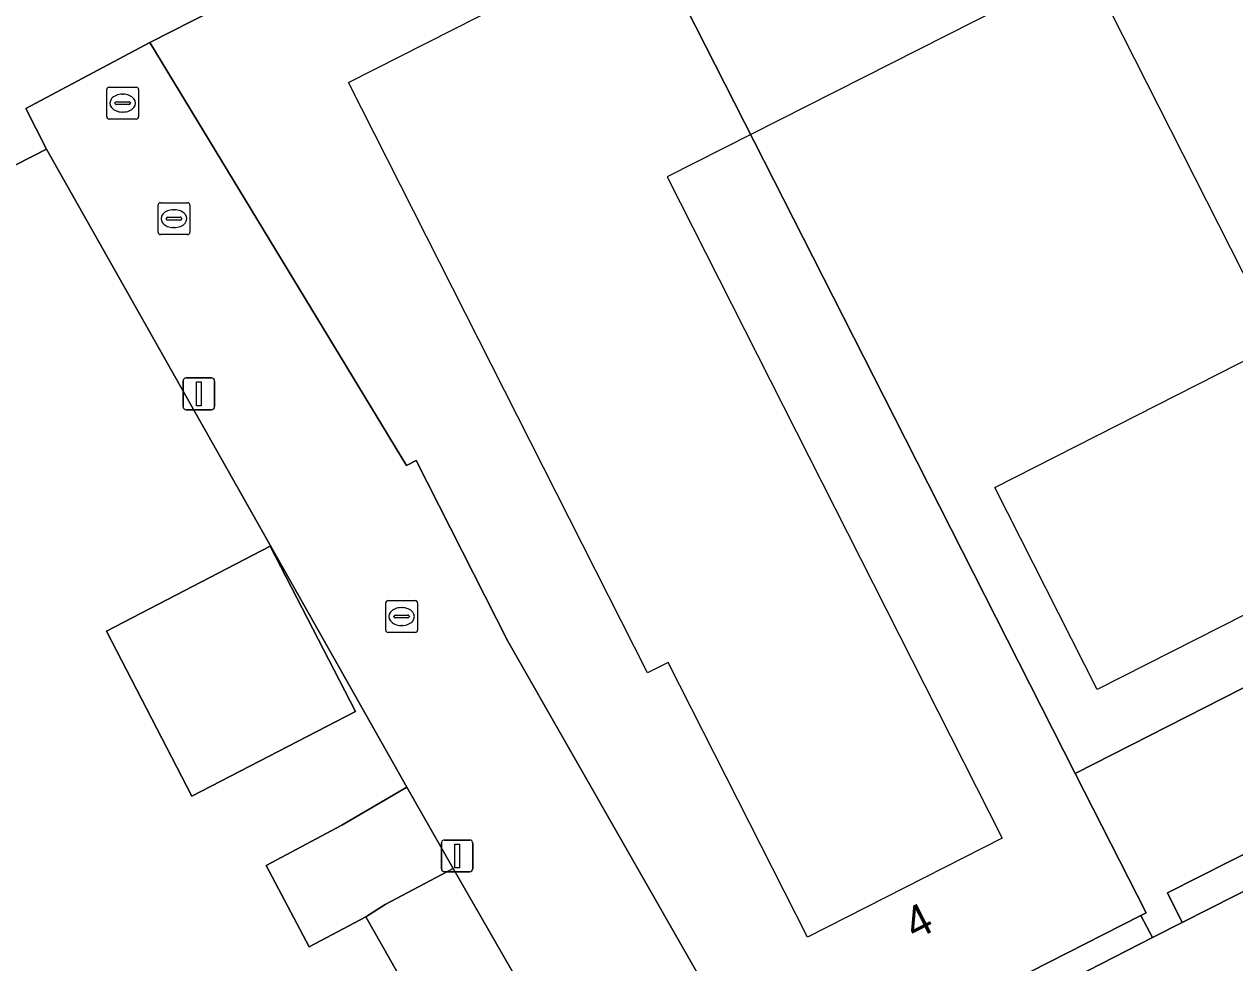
# Model space of a CAD drawing. Extents: x 159888 to 160761, y 384031 to 384750.
# Drawn here: x 160531.08 to 160569.11, y 384304.54 to 384334.01 of the extents above; entities that cross this region are included whole.
import ezdxf

# ---------------------------------------------------------------- set-up
doc = ezdxf.new("R2010")
doc.units = 0
for name, color, linetype in [('IMGEO_Erf', 7, 'Continuous'), ('IMGEO_Kolk', 7, 'Continuous'), ('IMGEO_Lichtmast', 7, 'Continuous'), ('IMGEO_Pand', 7, 'Continuous'), ('IMGEO_Pand_nummerreeks', 7, 'Continuous'), ('IMGEO_Pand_vergunning_verleend', 7, 'Continuous'), ('IMGEO_Rijbaan_lokaal_open', 7, 'Continuous'), ('IMGEO_Rioolput', 7, 'Continuous'), ('IMGEO_Voetpad_open', 7, 'Continuous')]:
    doc.layers.add(name, color=color, linetype=linetype)

msp = doc.modelspace()

# ---------------------------------------------------------------- linework, layer by layer
at = {"layer": 'IMGEO_Erf'}
for points in [[(160530.86, 384299.884), (160531.135, 384299.401), (160533.646, 384295.03), (160536.236, 384296.185), (160542.794, 384299.585), (160544.644, 384300.668), (160544.79, 384300.753), (160541.82, 384305.981), (160540.039, 384305.037), (160538.682, 384307.598), (160541.063, 384308.86), (160543.1, 384310.052), (160531.789, 384330.089), (160529.359, 384328.855)], [(160575.166, 384316.112), (160564.1, 384310.488), (160566.326, 384306.106), (160566.162, 384306.023), (160566.53, 384305.339), (160567.462, 384305.807), (160566.993, 384306.736), (160571.974, 384309.253)]]:
    msp.add_lwpolyline(points, dxfattribs=at)
msp.add_lwpolyline([(160538.814, 384317.617), (160541.492, 384312.435), (160536.346, 384309.775), (160533.668, 384314.957)], close=True, dxfattribs=at)
at = {"layer": 'IMGEO_Kolk'}
for p, q in [((160535.288, 384327.479), (160535.288, 384328.331)), ((160535.363, 384328.405), (160536.215, 384328.405)), ((160535.776, 384328.185), (160535.801, 384328.185)), ((160536.289, 384328.331), (160536.289, 384327.479)), ((160535.547, 384327.899), (160535.547, 384327.911)), ((160535.985, 384327.862), (160535.587, 384327.862)), ((160535.59, 384327.948), (160535.988, 384327.948)), ((160536.031, 384327.911), (160536.031, 384327.899)), ((160536.215, 384327.405), (160535.363, 384327.405)), ((160535.799, 384327.625), (160535.774, 384327.625)), ((160542.514, 384315.912), (160543.366, 384315.912)), ((160542.439, 384314.986), (160542.439, 384315.838)), ((160542.927, 384315.692), (160542.952, 384315.692)), ((160543.44, 384315.838), (160543.44, 384314.986)), ((160542.698, 384315.406), (160542.698, 384315.418)), ((160543.136, 384315.369), (160542.738, 384315.369)), ((160542.741, 384315.455), (160543.139, 384315.455)), ((160543.182, 384315.418), (160543.182, 384315.406)), ((160543.366, 384314.912), (160542.514, 384314.912)), ((160542.95, 384315.132), (160542.925, 384315.132))]:
    msp.add_line(p, q, dxfattribs=at)
for points in [[(160535.288, 384327.479), (160535.288, 384328.331)], [(160535.363, 384328.405), (160536.215, 384328.405)], [(160536.289, 384328.331), (160536.289, 384327.479)], [(160536.215, 384327.405), (160535.363, 384327.405)], [(160542.514, 384315.912), (160543.366, 384315.912)], [(160542.439, 384314.986), (160542.439, 384315.838)], [(160543.44, 384315.838), (160543.44, 384314.986)], [(160543.366, 384314.912), (160542.514, 384314.912)]]:
    msp.add_lwpolyline(points, dxfattribs=at)
for centre, radius, start, end in [((160535.365, 384328.329), 0.0765, 91.552, 178.448), ((160535.365, 384328.329), 0.0765, 91.552, 178.448), ((160536.213, 384328.329), 0.0765, 1.552, 88.448), ((160536.213, 384328.329), 0.0765, 1.552, 88.448), ((160535.587, 384327.908), 0.0403, 85.8775, 175.7526), ((160535.584, 384327.898), 0.0366, 178.938, 274.7102), ((160535.988, 384327.905), 0.043, 264.8664, 352.4533), ((160535.992, 384327.91), 0.0386, 1.7309, 96.639), ((160535.365, 384327.481), 0.0765, 181.552, 268.448), ((160535.365, 384327.481), 0.0765, 181.552, 268.448), ((160536.213, 384327.481), 0.0765, 271.552, 358.448), ((160536.213, 384327.481), 0.0765, 271.552, 358.448), ((160542.516, 384315.836), 0.0765, 91.552, 178.448), ((160542.516, 384315.836), 0.0765, 91.552, 178.448), ((160543.364, 384315.836), 0.0765, 1.552, 88.448), ((160543.364, 384315.836), 0.0765, 1.552, 88.448), ((160542.738, 384315.415), 0.0403, 85.8775, 175.7526), ((160542.735, 384315.405), 0.0366, 178.938, 274.7102), ((160543.139, 384315.412), 0.043, 264.8664, 352.4533), ((160543.143, 384315.417), 0.0386, 1.7309, 96.639), ((160542.516, 384314.988), 0.0765, 181.552, 268.448), ((160542.516, 384314.988), 0.0765, 181.552, 268.448), ((160543.364, 384314.988), 0.0765, 271.552, 358.448), ((160543.364, 384314.988), 0.0765, 271.552, 358.448)]:
    msp.add_arc(centre, radius, start, end, dxfattribs=at)
for centre, major_axis, ratio, start_param, end_param in [((160535.775, 384327.905), (-0.387, 0.002), 0.722429, 4.712389, 7.853982), ((160535.8, 384327.905), (-0.39, 0.002), 0.717154, 1.570796, 4.712389), ((160542.926, 384315.412), (-0.387, 0.002), 0.722429, 4.712389, 7.853982), ((160542.951, 384315.412), (-0.39, 0.002), 0.717154, 1.570796, 4.712389)]:
    msp.add_ellipse(centre, major_axis=major_axis, ratio=ratio, start_param=start_param, end_param=end_param, dxfattribs=at)
at = {"layer": 'IMGEO_Lichtmast'}
for p, q in [((160536.075, 384322.005), (160536.075, 384322.805)), ((160536.075, 384322.805), (160536.075, 384322.005)), ((160536.175, 384322.905), (160536.965, 384322.905)), ((160536.965, 384322.905), (160536.175, 384322.905)), ((160537.065, 384322.805), (160537.065, 384322.005)), ((160537.065, 384322.005), (160537.065, 384322.805)), ((160536.965, 384321.905), (160536.175, 384321.905)), ((160536.175, 384321.905), (160536.965, 384321.905)), ((160544.289, 384308.394), (160545.079, 384308.394)), ((160545.079, 384308.394), (160544.289, 384308.394)), ((160544.189, 384307.494), (160544.189, 384308.294)), ((160544.189, 384308.294), (160544.189, 384307.494)), ((160545.179, 384308.294), (160545.179, 384307.494)), ((160545.179, 384307.494), (160545.179, 384308.294)), ((160545.079, 384307.394), (160544.289, 384307.394)), ((160544.289, 384307.394), (160545.079, 384307.394))]:
    msp.add_line(p, q, dxfattribs=at)
for points in [[(160536.495, 384322.78), (160536.645, 384322.78), (160536.645, 384322.03), (160536.495, 384322.03), (160536.495, 384322.78)], [(160544.609, 384308.269), (160544.759, 384308.269), (160544.759, 384307.519), (160544.609, 384307.519), (160544.609, 384308.269)]]:
    msp.add_lwpolyline(points, dxfattribs=at)
for centre, start, end in [((160536.175, 384322.805), 90, 180), ((160536.175, 384322.805), 90, 180), ((160536.965, 384322.805), 0, 90), ((160536.965, 384322.805), 360, 90), ((160536.175, 384322.005), 180, 270), ((160536.175, 384322.005), 180, 270), ((160536.965, 384322.005), 270, 0), ((160536.965, 384322.005), 270, 0), ((160544.289, 384308.294), 90, 180), ((160544.289, 384308.294), 90, 180), ((160545.079, 384308.294), 0, 90), ((160545.079, 384308.294), 360, 90), ((160544.289, 384307.494), 180, 270), ((160544.289, 384307.494), 180, 270), ((160545.079, 384307.494), 270, 0), ((160545.079, 384307.494), 270, 0)]:
    msp.add_arc(centre, 0.1, start, end, dxfattribs=at)
at = {"layer": 'IMGEO_Pand'}
for points in [[(160548.767, 384340.417), (160548.858, 384340.463), (160553.091, 384332.138), (160555.55, 384327.303), (160558.407, 384321.685), (160564.1, 384310.488), (160575.166, 384316.112), (160574.426, 384317.567), (160579.619, 384320.206), (160579.931, 384319.59), (160581.061, 384320.164), (160580.788, 384320.701), (160582.016, 384321.325), (160583.665, 384318.082), (160588.311, 384320.443), (160585.604, 384324.648), (160574.55, 384342.177), (160568.09, 384352.422), (160548.143, 384341.701)], [(160543.753, 384337.869), (160541.644, 384342.015), (160526.798, 384333.902), (160529.359, 384328.855), (160531.789, 384330.089), (160531.14, 384331.368), (160535.033, 384333.437)], [(160548.767, 384340.417), (160543.753, 384337.869), (160535.033, 384333.437), (160543.096, 384320.156), (160543.393, 384320.307), (160546.274, 384314.638), (160552.084, 384304.47), (160554.565, 384300.129), (160555.152, 384300.427), (160566.162, 384306.023), (160566.326, 384306.106), (160564.1, 384310.488), (160558.407, 384321.685), (160555.55, 384327.303), (160553.091, 384332.138), (160548.858, 384340.463)], [(160538.814, 384317.617), (160533.668, 384314.957), (160536.346, 384309.775), (160541.492, 384312.435)], [(160543.1, 384310.052), (160541.063, 384308.86), (160538.682, 384307.598), (160540.039, 384305.037), (160541.82, 384305.981), (160542.425, 384306.371), (160544.563, 384307.504)], [(160544.563, 384307.504), (160542.425, 384306.371), (160541.82, 384305.981), (160544.79, 384300.753), (160547.519, 384302.353)]]:
    msp.add_lwpolyline(points, close=True, dxfattribs=at)
at = {"layer": 'IMGEO_Pand_vergunning_verleend'}
msp.add_lwpolyline([(160541.273, 384332.177), (160556.824, 384340.057), (160552.227, 384349.128), (160561.67, 384353.913), (160569.365, 384338.725), (160570.851, 384339.478), (160580.24, 384320.948), (160564.785, 384313.117), (160561.568, 384319.466), (160570.497, 384323.991), (160564.463, 384335.899), (160551.281, 384329.219), (160561.805, 384308.451), (160555.684, 384305.35), (160551.316, 384313.97), (160550.665, 384313.64)], close=True, dxfattribs=at)
at = {"layer": 'IMGEO_Rijbaan_lokaal_open'}
msp.add_lwpolyline([(160543.1, 384310.052), (160544.563, 384307.504), (160547.519, 384302.353), (160549.071, 384299.635), (160549.994, 384298.058), (160550.066, 384297.935), (160554.565, 384300.129), (160552.084, 384304.47), (160546.274, 384314.638), (160543.393, 384320.307), (160543.096, 384320.156), (160535.033, 384333.437), (160531.14, 384331.368), (160531.789, 384330.089)], close=True, dxfattribs=at)
msp.add_lwpolyline([(160612.124, 384331.359), (160596.143, 384321.577), (160595.889, 384321.422), (160590.108, 384317.85), (160586.028, 384315.337), (160572.443, 384308.324), (160567.462, 384305.807), (160566.53, 384305.339), (160555.538, 384299.708), (160550.478, 384297.137), (160546.731, 384295.217), (160546.235, 384294.964), (160538.022, 384290.775), (160536.409, 384289.932), (160530.529, 384286.928), (160530.447, 384286.864), (160533.164, 384281.656), (160533.808, 384281.997), (160534.575, 384282.359), (160579.578, 384305.42), (160588.356, 384309.89)], dxfattribs=at)
at = {"layer": 'IMGEO_Rioolput'}
for p, q in [((160533.677, 384331.107), (160533.677, 384331.959)), ((160533.752, 384332.033), (160534.604, 384332.033)), ((160534.678, 384331.959), (160534.678, 384331.107)), ((160533.936, 384331.527), (160533.936, 384331.539)), ((160533.979, 384331.576), (160534.377, 384331.576)), ((160534.165, 384331.813), (160534.19, 384331.813)), ((160534.42, 384331.539), (160534.42, 384331.527)), ((160534.374, 384331.49), (160533.976, 384331.49)), ((160534.188, 384331.253), (160534.163, 384331.253)), ((160534.604, 384331.033), (160533.752, 384331.033))]:
    msp.add_line(p, q, dxfattribs=at)
for points in [[(160533.677, 384331.107), (160533.677, 384331.959)], [(160533.752, 384332.033), (160534.604, 384332.033)], [(160534.678, 384331.959), (160534.678, 384331.107)], [(160534.604, 384331.033), (160533.752, 384331.033)]]:
    msp.add_lwpolyline(points, dxfattribs=at)
for centre, radius, start, end in [((160533.754, 384331.957), 0.0765, 91.552, 178.448), ((160533.754, 384331.957), 0.0765, 91.552, 178.448), ((160534.602, 384331.957), 0.0765, 1.552, 88.448), ((160534.602, 384331.957), 0.0765, 1.552, 88.448), ((160533.976, 384331.536), 0.0403, 85.8775, 175.7526), ((160533.973, 384331.526), 0.0366, 178.938, 274.7102), ((160534.377, 384331.533), 0.043, 264.8664, 352.4533), ((160534.381, 384331.538), 0.0386, 1.7309, 96.639), ((160533.754, 384331.109), 0.0765, 181.552, 268.448), ((160533.754, 384331.109), 0.0765, 181.552, 268.448), ((160534.602, 384331.109), 0.0765, 271.552, 358.448), ((160534.602, 384331.109), 0.0765, 271.552, 358.448)]:
    msp.add_arc(centre, radius, start, end, dxfattribs=at)
for centre, major_axis, ratio, start_param, end_param in [((160534.164, 384331.533), (-0.387, 0.002), 0.722429, 4.712389, 7.853982), ((160534.189, 384331.533), (-0.39, 0.002), 0.717154, 1.570796, 4.712389)]:
    msp.add_ellipse(centre, major_axis=major_axis, ratio=ratio, start_param=start_param, end_param=end_param, dxfattribs=at)
at = {"layer": 'IMGEO_Voetpad_open'}
for points in [[(160571.974, 384309.253), (160566.993, 384306.736), (160567.462, 384305.807), (160572.443, 384308.324)], [(160555.538, 384299.708), (160566.53, 384305.339), (160566.162, 384306.023), (160555.152, 384300.427)]]:
    msp.add_lwpolyline(points, close=True, dxfattribs=at)

# ---------------------------------------------------------------- texts
at = {"layer": 'IMGEO_Pand_nummerreeks'}
msp.add_text('4', height=1, rotation=26.9399, dxfattribs=at).set_placement((160559.059, 384305.24))

doc.saveas('drawing.dxf')
